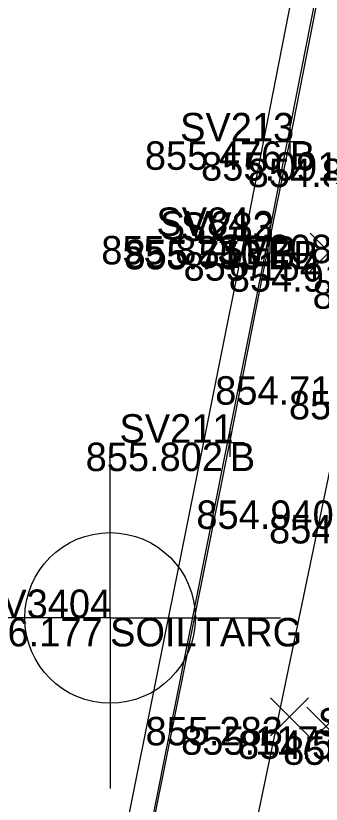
# Model space of a CAD drawing. Extents: x 2228183 to 2230895, y 679226 to 682223.
# Drawn here: x 2228313.99 to 2228324.74, y 680568.09 to 680595.81 of the extents above; entities that cross this region are included whole.
import ezdxf

# ---------------------------------------------------------------- set-up
doc = ezdxf.new("R2010")
doc.units = 0
for name, color, linetype in [('GT_Target_Soil_Boring', 7, 'Continuous'), ('PV_X_EOP', 7, 'Continuous'), ('PV_X_Shoulder_Aggregate', 7, 'Continuous'), ('RD_X_GR_Rt', 7, 'Continuous'), ('SC_Scratch1', 7, 'Continuous'), ('SV_P_Control_Cells_Set', 7, 'Continuous'), ('SV_X_Break_Lines', 7, 'Continuous'), ('SV_X_Random_Point', 7, 'Continuous'), ('SV_X_Shot_Marker', 7, 'Continuous'), ('SV_X_Text_Comment', 7, 'Continuous')]:
    doc.layers.add(name, color=color, linetype=linetype)

msp = doc.modelspace()

# ---------------------------------------------------------------- linework, layer by layer
at = {"layer": 'GT_Target_Soil_Boring'}
for q in [(2228317.313, 680580.641), (2228311.313, 680574.641), (2228317.313, 680568.641), (2228323.313, 680574.641)]:
    msp.add_line((2228317.313, 680574.641), q, dxfattribs=at)
msp.add_circle((2228317.313, 680574.641), 3, dxfattribs=at)
at = {"layer": 'PV_X_EOP'}
msp.add_lwpolyline([(2228272.958, 680193.788), (2228272.514, 680218.749), (2228272.761, 680243.66), (2228273.456, 680268.53), (2228274.726, 680293.686), (2228276.435, 680318.586), (2228278.817, 680343.424), (2228281.861, 680368.095), (2228285.158, 680392.512), (2228289.018, 680417.009), (2228293.5, 680441.465), (2228298.055, 680466.05), (2228302.846, 680490.329), (2228307.636, 680514.848), (2228312.366, 680539.332), (2228317.173, 680563.701), (2228322.066, 680588.07), (2228326.883, 680612.686), (2228331.837, 680637.002), (2228336.903, 680661.667), (2228341.796, 680685.984)], dxfattribs=at)
at = {"layer": 'PV_X_Shoulder_Aggregate'}
msp.add_lwpolyline([(2228273.386, 680193.772), (2228272.957, 680218.691), (2228273.264, 680243.644), (2228274.133, 680268.478), (2228275.472, 680293.621), (2228277.239, 680318.511), (2228279.649, 680343.317), (2228282.622, 680367.988), (2228285.854, 680392.371), (2228289.575, 680416.853), (2228293.89, 680441.38), (2228298.61, 680465.949), (2228303.2, 680490.238), (2228308.065, 680514.741), (2228313.026, 680539.169), (2228317.996, 680563.53), (2228322.869, 680587.896), (2228327.71, 680612.549), (2228332.443, 680636.855), (2228337.368, 680661.526), (2228342.398, 680685.817)], dxfattribs=at)
at = {"layer": 'RD_X_GR_Rt'}
msp.add_lwpolyline([(2228290.359, 680391.22), (2228294.274, 680415.932), (2228298.414, 680440.801), (2228302.718, 680465.177), (2228307.188, 680489.321), (2228312.206, 680513.859), (2228316.706, 680538.587), (2228321.519, 680562.878), (2228326.574, 680587.113), (2228331.32, 680611.864), (2228336.079, 680636.156), (2228341.093, 680660.882), (2228346.244, 680685.06), (2228350.849, 680709.572), (2228355.751, 680733.95), (2228357.804, 680743.718), (2228360.585, 680755.706), (2228364.08, 680768.892), (2228368.125, 680781.145)], dxfattribs=at)
at = {"layer": 'SV_X_Break_Lines'}
msp.add_lwpolyline([(2228318.056, 680563.531), (2228321.526, 680580.804), (2228322.934, 680587.943), (2228323.641, 680591.395), (2228326.787, 680607.417), (2228327.798, 680612.502), (2228328.969, 680618.417), (2228330.908, 680628.604), (2228332.526, 680636.825), (2228334.967, 680649.168), (2228337.431, 680661.516)], dxfattribs=at)
at = {"layer": 'SV_X_Random_Point'}
for p, q in [((2228324.352, 680586.831), (2228325.686, 680588.166)), ((2228324.352, 680588.166), (2228325.686, 680586.831)), ((2228322.957, 680570.496), (2228324.291, 680571.831)), ((2228322.957, 680571.831), (2228324.291, 680570.496)), ((2228324.242, 680570.166), (2228325.576, 680571.501)), ((2228324.242, 680571.501), (2228325.576, 680570.166))]:
    msp.add_line(p, q, dxfattribs=at)
at = {"layer": 'SV_X_Shot_Marker'}
for p, q in [((2228323.641, 680591.895), (2228323.641, 680590.895)), ((2228323.141, 680591.395), (2228324.141, 680591.395)), ((2228323.641, 680591.395), (2228323.641, 680591.395)), ((2228322.066, 680588.57), (2228322.066, 680587.57)), ((2228322.869, 680588.396), (2228322.869, 680587.396)), ((2228322.934, 680588.443), (2228322.934, 680587.443)), ((2228321.566, 680588.07), (2228322.566, 680588.07)), ((2228322.066, 680588.07), (2228322.066, 680588.07)), ((2228322.369, 680587.896), (2228323.369, 680587.896)), ((2228322.434, 680587.943), (2228323.434, 680587.943)), ((2228322.869, 680587.896), (2228322.869, 680587.896)), ((2228322.934, 680587.943), (2228322.934, 680587.943)), ((2228321.526, 680581.304), (2228321.526, 680580.304)), ((2228321.026, 680580.804), (2228322.026, 680580.804)), ((2228321.526, 680580.804), (2228321.526, 680580.804))]:
    msp.add_line(p, q, dxfattribs=at)

# ---------------------------------------------------------------- texts
at = {"layer": 'SC_Scratch1'}
for s, p in [('855.476', (2228318.537, 680590.395)), ('855.091', (2228320.515, 680590.014)), ('854.888', (2228322.157, 680589.788)), ('855.823', (2228317.002, 680587.07)), ('855.753', (2228317.805, 680586.896)), ('855.510', (2228317.821, 680586.943)), ('855.154', (2228319.897, 680586.498)), ('854.919', (2228321.49, 680586.113)), ('854.919', (2228321.49, 680586.113)), ('854.067', (2228324.438, 680585.51)), ('854.719', (2228321.013, 680582.139)), ('854.111', (2228323.608, 680581.621)), ('855.802', (2228316.453, 680579.804)), ('854.940', (2228320.35, 680577.772)), ('854.260', (2228322.907, 680577.26)), ('856.177', (2228312.217, 680573.641)), ('855.283', (2228318.56, 680570.163)), ('855.117', (2228319.813, 680569.833)), ('854.505', (2228321.814, 680569.686)), ('853.608', (2228323.403, 680569.479))]:
    msp.add_text(s, height=1, dxfattribs=at).set_placement(p)
at = {"layer": 'SV_P_Control_Cells_Set'}
for s, p in [('SV213', (2228319.777, 680591.395)), ('SV84', (2228318.942, 680588.07)), ('SV212', (2228319.061, 680587.943)), ('SV83', (2228319.803, 680587.896)), ('SV208_1', (2228321.109, 680587.113)), ('SV211', (2228317.644, 680580.804)), ('SV3404', (2228312.593, 680574.641)), ('SV339', (2228324.619, 680570.479))]:
    msp.add_text(s, height=1, dxfattribs=at).set_placement(p)
at = {"layer": 'SV_X_Text_Comment'}
for s, p in [('B', (2228323.641, 680590.395)), ('EP', (2228322.066, 680587.07)), ('EB', (2228322.869, 680586.896)), ('B', (2228322.934, 680586.943)), ('B', (2228321.526, 680579.804)), ('SOILTARG', (2228317.313, 680573.641))]:
    msp.add_text(s, height=1, dxfattribs=at).set_placement(p)

doc.saveas('drawing.dxf')
